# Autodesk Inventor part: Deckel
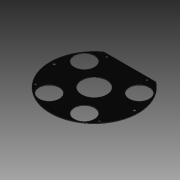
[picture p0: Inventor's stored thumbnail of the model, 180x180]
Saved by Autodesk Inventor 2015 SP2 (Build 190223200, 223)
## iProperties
Created: 2012-10
Part Number: Deckel
Material: PMMA-Kunststoff
Document SubType Name: Modeling
Designer: SteffenHaase
Density: 1.188 g/cm^3
Mass: 30.7432 g
Surface Area: 339.913 cm^2
Volume: 25.8782 cm^3
Appearance: Glatt - schwarz
Author: SteffenHaase
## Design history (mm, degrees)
sketch "Skizze1"
  geometry: L1 (-51.99, 71)-(51.99, 71); A1 r 88 centre (0, 0) between (-51.99, 71) and (51.99, 71); 1 further point
  constraints: 2 end point, 2 point on circle, 1 centre point, 1 coincident, 1 horizontal
  dimensions: "d2" = 176 diameter of A1; "d3" = 71 distance from line of point (0, 0) L1
extrude "Extrusion1" new body sketch "Skizze1" distance "d5" = 1; taper "d6" = 0 deg
sketch "Skizze2"
  geometry: L1 (-123.2, 0)-(123.2, 0) reference; L2 (0, -119.8)-(0, 102.8) reference; L3 (0, 0)-(-54.772, 35); L4 (-54.772, 35)-(0, 0); L5 (-35, -54.772)-(0, 0); C1 r 25 at (0, 0); C2 r 20 at (-54.772, 35); C3 r 20 at (54.772, 35); C4 r 20 at (35, -54.772); C5 r 20 at (-35, -54.772); A1 r 88 centre (0, 0) between (-51.99, 71) and (51.99, 71) reference
  constraints: 6 end point, 5 centre point, 1 coincident, 1 collinear
  dimensions: "d57" = 50 diameter of C1; "d59" = 35 distance from line of L3.end L1; "d60" = 35 distance from line of L1 C3.centre (= d59); "d61" = 54.772 distance from line of L3.end L2; "d62" = 40 diameter of C2; "d63" = 54.772 distance from line of C3.centre L2 (= d61); "d64" = 54.772 distance from line of C4.centre L1 (= d61); "d65" = 35 distance from line of L2 C4.centre (= d59); "d66" = 54.772 distance from line of L5.start L1 (= d61); "d67" = 35 distance from line of L2 L5.start (= d59); "d68" = 40 diameter of C5 (= d62); "d69" = 40 diameter of C3 (= d62); "d70" = 40 diameter of C4 (= d62)
extrude "Extrusion2" cut sketch "Skizze2" stored distance "d7" = 3; taper "d8" = 0 deg
sketch "Skizze6"
  geometry: L1 (0, 0)-(-63.582, -53.351); L2 (0, 0)-(63.582, -53.351); L3 (-123.2, 0)-(123.2, 0) reference; L4 (-40, 65)-(40, 65); L5 (0, 117.2)-(0, -122.2) reference; A1 r 88 centre (0, 0) between (-51.99, 71) and (51.99, 71) reference; A2 r 83 centre (0, 0) between (-63.582, -53.351) and (63.582, -53.351); 4 further points
  constraints: 6 end point, 5 coincident, 2 point on circle, 1 centre point, 1 parallel, 1 symmetric about line
  dimensions: "d72" = 166 diameter of A2; "d73" = 40 deg angle of L3 L1; "d75" = 40 deg angle of L2 L3 (= d73); "d77" = 80 distance of L4.start L4.end; "d78" = 65 distance between parallel lines of L3 L4
hole "Bohrung4" sketch "Skizze6" at (-63.582, -53.351), (63.582, -53.351), (-40, 65), (40, 65) diameter "d79" = 3.1; stored, may be unused: countersink angle "d83" = 90 deg, drill point angle "d85" = 118 deg; dims "d80" = 6, "d81" = 4, "d82" = 2, "d84" = 8
sketch "Skizze7"
  geometry: L1 (-123.2, 0)-(123.2, 0) reference; L2 (0, 102.8)-(0, -119.8) reference; 3 further points
  constraints: 2 point on line, 1 symmetric about line
  dimensions: "d89" = 160 distance of point (80, 0) point (-80, 0)
hole "Bohrung5" sketch "Skizze7" at (-80, 0), (80, 0) diameter "d90" = 4.2; stored, may be unused: countersink angle "d94" = 90 deg, drill point angle "d96" = 118 deg; dims "d91" = 6, "d92" = 40, "d93" = 1, "d95" = 8
node "Volumenkörper1"
